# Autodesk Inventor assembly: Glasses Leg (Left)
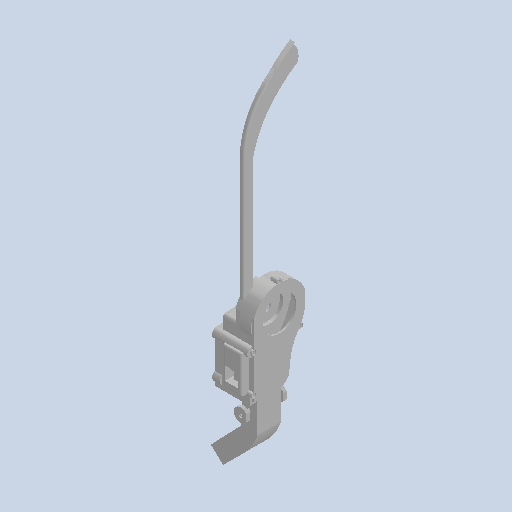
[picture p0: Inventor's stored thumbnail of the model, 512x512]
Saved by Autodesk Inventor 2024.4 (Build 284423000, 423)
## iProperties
Created: 2025-05
Part Number: Glasses Leg (Left)
Document SubType Name: Assembly
Designer: AdminForWorker
Title: Glasses Leg (Left) v61
Author: AdminForWorker
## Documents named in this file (4)
- c:\worker\convert-fusion-r02-cosv3\tmp\job-1\2\temp\files\be827049-a7f2-47ea-a815-8d9efd6bfce9\Glasses Leg (Left) v61.iam
- c:\worker\convert-fusion-r02-cosv3\tmp\job-1\2\temp\files\be827049-a7f2-47ea-a815-8d9efd6bfce9\XIAO-ESP32S3-Sense-housing-design(bottom) v4.iam
- c:\worker\convert-fusion-r02-cosv3\tmp\job-1\2\temp\files\be827049-a7f2-47ea-a815-8d9efd6bfce9\CameraHold4.0 v2.ipt
- c:\worker\convert-fusion-r02-cosv3\tmp\job-1\2\temp\files\be827049-a7f2-47ea-a815-8d9efd6bfce9\Part6.ipt
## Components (3 placed, 3 different names)
1. XIAO-ESP32S3-Sense-housing-design(bottom) v4:1 [sub-assembly]
2. CameraHold4.0 v2:1
3. Part6
